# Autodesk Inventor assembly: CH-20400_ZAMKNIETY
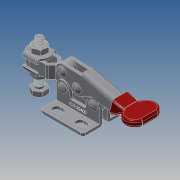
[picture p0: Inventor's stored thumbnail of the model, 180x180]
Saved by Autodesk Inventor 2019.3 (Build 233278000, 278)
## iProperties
Company: Î¢ÈíÖÐ¹ú
Created: 2012-09
Part Number: CH-20400_ZAMKNIETY
Material: Ogólny
Description: STEP AP203
Document SubType Name: Assembly
Designer: CADENGINEERING4
Sending System: SolidWorks 2010
Preprocessor: SwSTEP 2.0
Title: CH-20400.STEP
Author: Î¢ÈíÓÃ»§
Revision Number: ÈÎºÎ
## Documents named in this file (9)
- E:\STRONA\Horizontal toggle clamp\CH-20400\CH-20400_ZAMKNIETY.iam
- E:\STRONA\Horizontal toggle clamp\CH-20400\CH-20400-05.ipt
- E:\STRONA\Horizontal toggle clamp\CH-20400\CH-FW-080.ipt
- E:\STRONA\Horizontal toggle clamp\CH-20400\CH-20400-02 U-BAR.ipt
- E:\STRONA\Horizontal toggle clamp\CH-20400\CH-20400-03 HANDLE.ipt
- E:\STRONA\Horizontal toggle clamp\CH-20400\CH-20400-04 CONNECTING-PLATE.ipt
- E:\STRONA\Horizontal toggle clamp\CH-20400\M4 Nut.ipt
- E:\STRONA\Horizontal toggle clamp\CH-20400\CH-SA-042507 SPINDLE SUPPLIED.ipt
- E:\STRONA\Horizontal toggle clamp\CH-20400\CH-20400-01 FLANGED BASE.ipt
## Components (14 placed, 14 different names)
1. CH-20400-05_1 — Zestawiające:15, Zestawiające:16
2. CH-20400-05_2 — Zestawiające:23, Zestawiające:24
3. CH-FW-080_3 — Równoległe:2, Zestawiające:6, Zestawiające:7, Zestawiające:8
4. CH-20400-02 U-BAR_4 — Równoległe:1, Zestawiające:4, Zestawiające:8, Zestawiające:9, Zestawiające:21, Zestawiające:22, Zestawiające:25
5. CH-20400-03 HANDLE_5 — Zestawiające:17, Zestawiające:18, Zestawiające:19, Zestawiające:20, Zestawiające:25, Zestawiające:26, Zestawiające:27, Przejściowe:1
6. CH-20400-04 CONNECTING-PLATE_6 — Zestawiające:10, Zestawiające:11, Zestawiające:12, Zestawiające:17
7. CH-20400-05_7 — Zestawiające:19, Zestawiające:20
8. M4 Nut_8 — Zestawiające:1, Zestawiające:3
9. CH-SA-042507 SPINDLE SUPPLIED_9 — Równoległe:3, Zestawiające:1, Zestawiające:2, Zestawiające:5, Zestawiające:6, Zestawiające:9
10. CH-FW-080_10 — Równoległe:1, Równoległe:2, Zestawiające:2, Zestawiające:3, Zestawiające:4
11. CH-20400-01 FLANGED BASE_11 — Zestawiające:13, Zestawiające:14, Zestawiające:15, Zestawiające:16, Zestawiające:21, Zestawiające:22, Zestawiające:23, Zestawiające:24, Przejściowe:1
12. CH-20400-05_12 — Zestawiające:26, Zestawiające:27
13. CH-20400-04 CONNECTING-PLATE_13 — Zestawiające:10, Zestawiające:11, Zestawiające:12, Zestawiające:13, Zestawiające:14, Zestawiające:18
14. M4 Nut_14 — Równoległe:3, Zestawiające:5, Zestawiające:7
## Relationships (31: Mate 27, Flush 3, Transitional 1)
- Równoległe:1 [Flush]: CH-20400-02 U-BAR_4 ↔ CH-FW-080_10
- Równoległe:2 [Flush]: CH-FW-080_3 ↔ CH-FW-080_10
- Równoległe:3 [Flush]: CH-SA-042507 SPINDLE SUPPLIED_9 ↔ M4 Nut_14
- Zestawiające:1 [Mate]: M4 Nut_8 ↔ CH-SA-042507 SPINDLE SUPPLIED_9
- Zestawiające:2 [Mate]: CH-SA-042507 SPINDLE SUPPLIED_9 ↔ CH-FW-080_10
- Zestawiające:3 [Mate]: M4 Nut_8 ↔ CH-FW-080_10
- Zestawiające:4 [Mate]: CH-20400-02 U-BAR_4 ↔ CH-FW-080_10
- Zestawiające:5 [Mate]: CH-SA-042507 SPINDLE SUPPLIED_9 ↔ M4 Nut_14
- Zestawiające:6 [Mate]: CH-FW-080_3 ↔ CH-SA-042507 SPINDLE SUPPLIED_9
- Zestawiające:7 [Mate]: CH-FW-080_3 ↔ M4 Nut_14
- Zestawiające:8 [Mate]: CH-FW-080_3 ↔ CH-20400-02 U-BAR_4
- Zestawiające:9 [Mate]: CH-20400-02 U-BAR_4 ↔ CH-SA-042507 SPINDLE SUPPLIED_9
- Zestawiające:10 [Mate]: CH-20400-04 CONNECTING-PLATE_6 ↔ CH-20400-04 CONNECTING-PLATE_13
- Zestawiające:11 [Mate]: CH-20400-04 CONNECTING-PLATE_6 ↔ CH-20400-04 CONNECTING-PLATE_13
- Zestawiające:12 [Mate]: CH-20400-04 CONNECTING-PLATE_6 ↔ CH-20400-04 CONNECTING-PLATE_13
- Zestawiające:13 [Mate]: CH-20400-01 FLANGED BASE_11 ↔ CH-20400-04 CONNECTING-PLATE_13
- Zestawiające:14 [Mate]: CH-20400-01 FLANGED BASE_11 ↔ CH-20400-04 CONNECTING-PLATE_13
- Zestawiające:15 [Mate]: CH-20400-05_1 ↔ CH-20400-01 FLANGED BASE_11
- Zestawiające:16 [Mate]: CH-20400-05_1 ↔ CH-20400-01 FLANGED BASE_11
- Zestawiające:17 [Mate]: CH-20400-03 HANDLE_5 ↔ CH-20400-04 CONNECTING-PLATE_6
- Zestawiające:18 [Mate]: CH-20400-03 HANDLE_5 ↔ CH-20400-04 CONNECTING-PLATE_13
- Zestawiające:19 [Mate]: CH-20400-03 HANDLE_5 ↔ CH-20400-05_7
- Zestawiające:20 [Mate]: CH-20400-03 HANDLE_5 ↔ CH-20400-05_7
- Zestawiające:21 [Mate]: CH-20400-02 U-BAR_4 ↔ CH-20400-01 FLANGED BASE_11
- Zestawiające:22 [Mate]: CH-20400-02 U-BAR_4 ↔ CH-20400-01 FLANGED BASE_11
- Zestawiające:23 [Mate]: CH-20400-05_2 ↔ CH-20400-01 FLANGED BASE_11
- Zestawiające:24 [Mate]: CH-20400-05_2 ↔ CH-20400-01 FLANGED BASE_11
- Zestawiające:25 [Mate]: CH-20400-02 U-BAR_4 ↔ CH-20400-03 HANDLE_5
- Zestawiające:26 [Mate]: CH-20400-03 HANDLE_5 ↔ CH-20400-05_12
- Zestawiające:27 [Mate]: CH-20400-03 HANDLE_5 ↔ CH-20400-05_12
- Przejściowe:1 [Transitional]: CH-20400-03 HANDLE_5 ↔ CH-20400-01 FLANGED BASE_11
